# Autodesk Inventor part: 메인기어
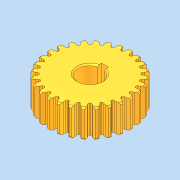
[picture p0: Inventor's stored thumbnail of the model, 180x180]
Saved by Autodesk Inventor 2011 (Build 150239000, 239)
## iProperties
Company: 한국ATC센터
Created: 2014-12
Part Number: 메인기어
Document SubType Name: Modeling
Designer: KYOUNG IL JANG
Density: 1 g/cm^3
Mass: 43.883 g
Surface Area: 122.661 cm^2
Volume: 43.883 cm^3
Author: KYOUNG IL JANG
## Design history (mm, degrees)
sketch "스케치1"
  geometry: C1 r 25.5 at (0, 0); A1 r 1.064 centre (-2.94, 26.392) between (-2.696, 25.357) and (-1.877, 26.361); A2 r 6.991 centre (5.094, 25.835) between (-1.626, 27.763) and (-1.877, 26.361); A3 r 11.864 centre (9.774, 24.478) between (-0.731, 29.991) and (-1.626, 27.763); A4 r 1.064 centre (2.94, 26.392) between (1.877, 26.361) and (2.696, 25.357); A5 r 6.991 centre (-5.094, 25.835) between (1.877, 26.361) and (1.626, 27.763); A6 r 11.864 centre (-9.774, 24.478) between (1.626, 27.763) and (0.731, 29.991); A7 r 25.5 centre (0, 0) between (2.696, 25.357) and (-2.696, 25.357); A8 r 30 centre (0, 0) between (0.731, 29.991) and (-0.731, 29.991); 1 further point
  constraints: 16 point on circle, 9 centre point, 2 coincident, 1 concentric
extrude "돌출1" new body sketch "스케치1" stored distance "d0" = 20; taper "d1" = 0 deg
extrude "돌출2" join sketch "스케치1" stored distance "d2" = 20; taper "d3" = 0 deg
chamfer "모따기1" distance "d4" = 1; stored, may be unused: second distance "d5" = 2, angle "d6" = 45 deg
hole "구멍1" diameter "d12" = 17; stored, may be unused: countersink angle "d16" = 90 deg, drill point angle "d18" = 118 deg; dims "d10" = 10, "d11" = 10, "d13" = 6, "d14" = 4, "d15" = 2, "d17" = 8
sketch "스케치2"
  geometry: L1 (-2.5, 8.124)-(-2.5, 10.8); L2 (-2.5, 10.8)-(2.5, 10.8); L3 (2.5, 10.8)-(2.5, 8.124); A1 r 8.5 centre (0, 0) between (-2.5, 8.124) and (2.5, 8.124) reference; 1 further point
  constraints: 6 end point, 2 parallel, 2 point on circle, 1 perpendicular, 1 vertical
  dimensions: "d19" = 5 distance of L1.end L2.end; "d20" = 2.3 distance edge to line of A1 L2
extrude "돌출3" cut sketch "스케치2" stored distance "d21" = 20; taper "d22" = 0 deg
chamfer "모따기2" distance "d23" = 1; stored, may be unused: second distance "d24" = 2, angle "d25" = 45 deg
node "솔리드1"
pattern_circular "원형 패턴1" dims angle "d8" = 360 deg
